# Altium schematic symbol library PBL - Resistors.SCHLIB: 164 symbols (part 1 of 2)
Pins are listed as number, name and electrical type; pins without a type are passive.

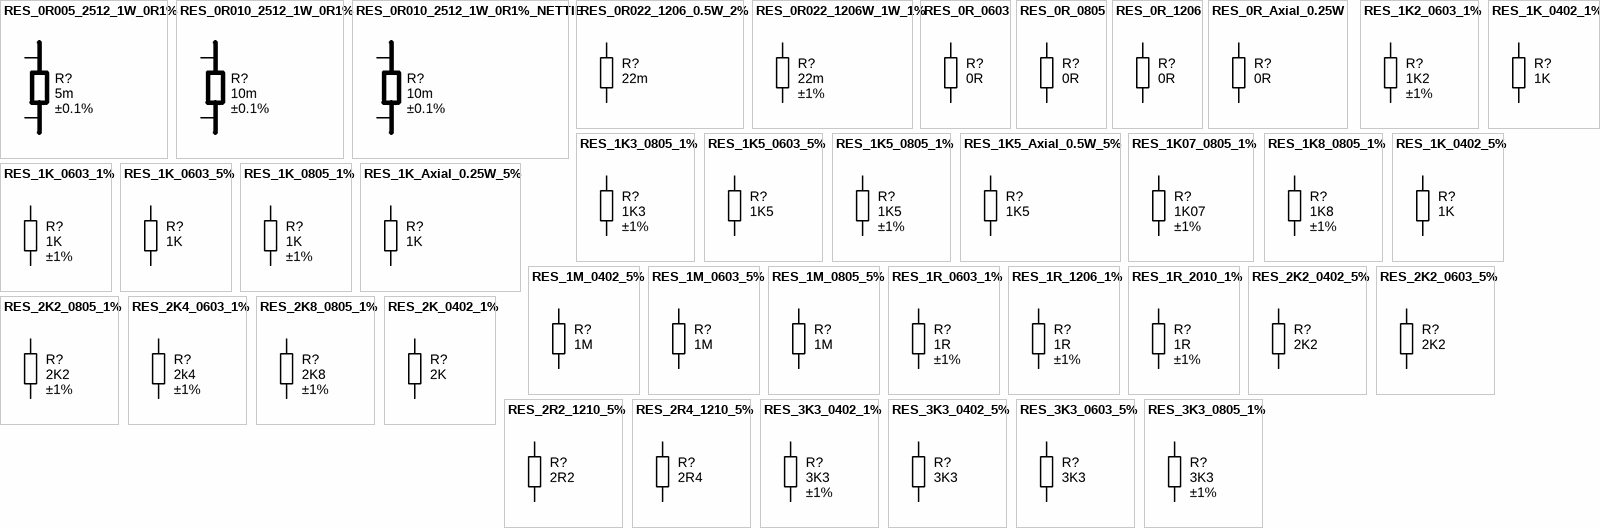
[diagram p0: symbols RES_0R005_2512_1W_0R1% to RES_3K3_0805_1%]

## RES_0R005_2512_1W_0R1%
designator R?, comment value 5m  Tolerance: ±0.1%  (hidden comment: Metal Foil with Kelvin terminations)
RES 0.005 OHM 1W 0.1% 2512 SMD; Manufacturer 1: Vishay Foil Resistors (Division of VPG); Manufacturer Part Number 1: Y14870R00500B9W; Temperature Coefficient: ±15ppm/°C; SCDType: undef
footprint RESC6332X89_SENSE (SMD Sense Resistor with Kelvin terminations, Body 6.3x3.2mm, 2512, IPC Medium Density)
pins: E1 S, E2 S, I1 I, I2 I

## RES_0R010_2512_1W_0R1%
designator R?, comment value 10m  Tolerance: ±0.1%  (hidden comment: Metal Foil with Kelvin terminations)
RES 0.010 OHM 1W 0.1% 2512 SMD; Manufacturer 1: Vishay Foil Resistors (Division of VPG); Manufacturer Part Number 1: Y14870R01000B9W; Temperature Coefficient: ±15ppm/°C; SCDType: undef
footprint RESC6332X89_SENSE (SMD Sense Resistor with Kelvin terminations, Body 6.3x3.2mm, 2512, IPC Medium Density)
pins: E1 S, E2 S, I1 I, I2 I

## RES_0R010_2512_1W_0R1%_NETTIE
designator R?, comment value 10m  Tolerance: ±0.1%  (hidden comment: Metal Foil with Kelvin terminations)  (net tie, no BOM)
RES 0.010 OHM 1W 0.1% 2512 SMD; Manufacturer 1: Vishay Foil Resistors (Division of VPG); Manufacturer Part Number 1: Y14870R01000B9W; Temperature Coefficient: ±15ppm/°C; SCDType: undef
footprint RESC6332X89_SENSE_NETTIE (SMD Sense Resistor with Kelvin terminations, Body 6.3x3.2mm, 2512, IPC Medium Density)
pins: E1 S, E2 S, I1 I, I2 I

## RES_0R022_1206_0.5W_2%
designator R?, comment value 22m  (hidden comment: Thick Film)
Resistor SMD chip 22 milliohm 0.5W 2% 1206; Manufacturer 1: Susumu Co Ltd; Manufacturer Part Number 1: RL1632T-R022-G; Ratings: 1/2W; SCDType: spec
footprint RESC3216X70N (Chip Resistor, Body 3.2x1.6mm, 1206, IPC Medium Density)
pins: 1, 2

## RES_0R022_1206W_1W_1%
designator R?, comment value 22m  Tolerance: ±1%  (hidden comment: Thick film)
RES .022 OHM 1W 1% 1206 SMD; Manufacturer 1: Susumu Co Ltd; Manufacturer Part Number 1: PRL1632-R022-F-T1; Temperature Coefficient: ±100ppm/°C; SCDType: undef
footprint RESC3216X70N (Chip Resistor, Body 3.2x1.6mm, 1206, IPC Medium Density)
pins: 1, 2

## RES_0R_0603
designator R?, comment value 0R  (hidden comment: Thick Film)
Resistor SMD chip 0.0 Ohm 0.1W 0603; Manufacturer 1: Vishay/Dale; Manufacturer Part Number 1: CRCW06030000Z0EA; Tolerance: ±5%; Ratings: 1/10W; SCDType: spec
footprint RESC1608N_ZERO (Chip Resistor, Body 1.6x0.8mm, 0603, IPC Medium Density)
pins: 1, 2

## RES_0R_0805
designator R?, comment value 0R  (hidden comment: Jumper)
Resistor SMD chip 0.0 Ohm 0.125W 0805; Manufacturer 1: Samsung Electro-Mechanics America, Inc; Manufacturer Part Number 1: RC2012J000CS; Ratings: 1/8W; SCDType: spec
footprint RESC2012N_ZERO (Chip Resistor, Body 2.0x1.2mm, 0805, IPC Medium Density)
pins: 1, 2

## RES_0R_1206
designator R?, comment value 0R  (hidden comment: Thick Film)
Resistor SMD chip 0.0 Ohm 0.25W 1206; Manufacturer 1: Vishay/Dale; Manufacturer Part Number 1: CRCW12060000Z0EA; Tolerance: ±5%; Ratings: 1/4W; SCDType: spec*\?
footprint RESC3216N_ZERO (Chip Resistor, Body 3.2x1.6mm, 1206, IPC Medium Density)
pins: 1, 2

## RES_0R_Axial_0.25W
designator R?, comment value 0R  (hidden comment: Carbon Film)
Resistor THD 0.0 Ohm 0.25W Jumper; Manufacturer 1: Yageo; Manufacturer Part Number 1: ZOR-25-R; Ratings: 1/4W; SCDType: spec
footprint RESTH_0.0R_AXIAL-0.6 (Axial Resistor 0 Ohm, Thru-Hole; 2 Leads; 0.6 in Pin Spacing)
pins: 1, 2

## RES_1K2_0603_1%
designator R?, comment value 1K2  Tolerance: ±1%  (hidden comment: Thick Film)
Resistor SMD chip 1.2K Ohm 0.1W 1% 0603; Manufacturer: Yageo; Manufacturer Part Number: RC0603FR-071K2L; Ratings: 1/10W; SCDType: undef
footprint RESC1608X55N (Chip Resistor, Body 1.6x0.8mm, 0603, IPC Medium Density)
pins: 1, 2

## RES_1K3_0805_1%
designator R?, comment value 1K3  Tolerance: ±1%  (hidden comment: Thick Film)
Resistor SMD chip 1.3k Ohm 0.125W 1% 0805; Manufacturer 1: Vishay/Dale; Manufacturer Part Number 1: CRCW08051K30FKEA; Ratings: 1/8W; SCDType: spec
footprint RESC2012X70N (Chip Resistor, Body 2.0x1.2mm, 0805, IPC Medium Density)
pins: 1, 2

## RES_1K5_0603_5%
designator R?, comment value 1K5  (hidden comment: Thick Film)
Resistor SMD chip 1.5k Ohm 0.1W 5% 0603; Manufacturer 1: Yageo; Manufacturer Part Number 1: RC0603JR-071K5L; Ratings: 1/10 W; SCDType: spec
footprint RESC1608X55N (Chip Resistor, Body 1.6x0.8mm, 0603, IPC Medium Density)
pins: 1, 2

## RES_1K5_0805_1%
designator R?, comment value 1K5  Tolerance: ±1%  (hidden comment: Thick Film)
Resistor SMD chip 1.5k Ohm 0.125W 1% 0805; Manufacturer 1: Vishay/Dale; Manufacturer Part Number 1: CRCW08051K50FKEA; Ratings: 1/8W; SCDType: spec
footprint RESC2012X70N (Chip Resistor, Body 2.0x1.2mm, 0805, IPC Medium Density)
pins: 1, 2

## RES_1K5_Axial_0.5W_5%
designator R?, comment value 1K5  (hidden comment: Carbon Film)
Resistor THD Axial 1.5k Ohm 0.5W 5% Carbon Film; Manufacturer 1: Yageo; Manufacturer Part Number 1: CFR-50JB-1K5; Ratings: 1/2W; SCDType: spec
footprint RESTH_AXIAL-0.4
pins: 1, 2

## RES_1K07_0805_1%
designator R?, comment value 1K07  Tolerance: ±1%  (hidden comment: Thick Film)
Resistor SMD chip 1.07K Ohm 0.125W 1% 0805; Manufacturer 1: Panasonic Electronic Components; Manufacturer Part Number 1: ERJ-6ENF1071V; Ratings: 1/8W; SCDType: undef
footprint RESC2012X70N (Chip Resistor, Body 2.0x1.2mm, 0805, IPC Medium Density)
pins: 1, 2

## RES_1K8_0805_1%
designator R?, comment value 1K8  Tolerance: ±1%  (hidden comment: Thick Film)
Resistor SMD chip 1.8k Ohm 0.125W 1% 0805; Manufacturer 1: Vishay/Dale; Manufacturer Part Number 1: CRCW08051K80FKEA; Ratings: 1/8W; SCDType: spec
footprint RESC2012X70N (Chip Resistor, Body 2.0x1.2mm, 0805, IPC Medium Density)
pins: 1, 2

## RES_1K_0402_1%
designator R?, comment value 1K  (hidden comment: Thick Film)
Resistor SMD chip 1k Ohm 0.063W 1% 0402; Manufacturer 1: ROhm; Manufacturer Part Number 1: MCR01MRTF1001; Ratings: 1/16 W; SCDType: spec
footprint RESC1005X40N (Chip Resistor, Body 1.0x0.5mm, EIA 0402, IPC Medium Density)
pins: 1, 2

## RES_1K_0402_5%
designator R?, comment value 1K  (hidden comment: Thick Film)
Resistor SMD chip 1k Ohm 0.063W 5% 0402; Manufacturer 1: Yageo; Manufacturer Part Number 1: RC0402JR-071KL; Ratings: 1/16 W; SCDType: spec
footprint RESC1005X40N (Chip Resistor, Body 1.0x0.5mm, EIA 0402, IPC Medium Density)
pins: 1, 2

## RES_1K_0603_1%
designator R?, comment value 1K  Tolerance: ±1%  (hidden comment: Thick Film)
Resistor SMD chip 1k Ohm 0.1W 1% 0603; Manufacturer 1: Yageo; Manufacturer Part Number 1: RC0603FR-071KL; Ratings: 1/10W; SCDType: spec
footprint RESC1608X55N (Chip Resistor, Body 1.6x0.8mm, 0603, IPC Medium Density)
pins: 1, 2

## RES_1K_0603_5%
designator R?, comment value 1K  (hidden comment: Thick Film)
Resistor SMD chip 1k Ohm 0.1W 5% 0603; Manufacturer 1: Yageo; Manufacturer Part Number 1: RC0603JR-071KL; Ratings: 1/10 W; SCDType: spec
footprint RESC1608X55N (Chip Resistor, Body 1.6x0.8mm, 0603, IPC Medium Density)
pins: 1, 2

## RES_1K_0805_1%
designator R?, comment value 1K  Tolerance: ±1%  (hidden comment: Thick Film)
Resistor SMD chip 1k Ohm 0.125W 1% 0805; Manufacturer 1: Vishay/Dale; Manufacturer Part Number 1: CRCW08051K00FKEA; Ratings: 1/8W; SCDType: spec
footprint RESC2012X70N (Chip Resistor, Body 2.0x1.2mm, 0805, IPC Medium Density)
pins: 1, 2

## RES_1K_Axial_0.25W_5%
designator R?, comment value 1K  (hidden comment: Carbon Film)
Resistor THD Axial 1k Ohm 0.25W 5% Carbon Film; Manufacturer 1: Yageo; Manufacturer Part Number 1: CFR-25JB-1K0; Ratings: 1/4W; SCDType: spec
footprint RESTH_AXIAL-0.4
pins: 1, 2

## RES_1M_0402_5%
designator R?, comment value 1M  (hidden comment: Thick Film)
Resistor SMD chip 1M Ohm 0.063W 5% 0402; Manufacturer 1: Vishay Dale; Manufacturer Part Number 1: CRCW04021M00JNED; Ratings: 1/16 W; Power Rating: 0.063W, 1/16W; SCDType: spec
footprint RESC1005X40N (Chip Resistor, Body 1.0x0.5mm, EIA 0402, IPC Medium Density)
pins: 1, 2

## RES_1M_0603_5%
designator R?, comment value 1M  (hidden comment: Thick Film)
Resistor SMD chip 1M Ohm 0.1W 5% 0603; Manufacturer 1: Vishay Dale; Manufacturer Part Number 1: CRCW06031M00JNEA; Ratings: 1/10 W; SCDType: spec
footprint RESC1608X55N (Chip Resistor, Body 1.6x0.8mm, 0603, IPC Medium Density)
pins: 1, 2

## RES_1M_0805_5%
designator R?, comment value 1M  (hidden comment: Thick Film)
Resistor SMD chip 1M Ohm 0.125W 5% 0805; Manufacturer 1: Vishay/Dale; Manufacturer Part Number 1: CRCW08051M00JNEA; Ratings: 1/8W; SCDType: spec
footprint RESC2012X70N (Chip Resistor, Body 2.0x1.2mm, 0805, IPC Medium Density)
pins: 1, 2

## RES_1R_0603_1%
designator R?, comment value 1R  Tolerance: ±1%  (hidden comment: Thick Film)
Resistor SMD chip 1 Ohm 0.1W 1% 0603; Manufacturer 1: Yageo; Manufacturer Part Number 1: RC0603FR-071RL; Ratings: 1/10W; SCDType: spec
footprint RESC1608X55N (Chip Resistor, Body 1.6x0.8mm, 0603, IPC Medium Density)
pins: 1, 2

## RES_1R_1206_1%
designator R?, comment value 1R  Tolerance: ±1%  (hidden comment: Thick Film)
Resistor SMD chip 1 Ohm 250mW 1% 1206; Manufacturer 1: KOA Speer; Manufacturer Part Number 1: RK73H2BTTD1R00F; Ratings: 1/4W; 200V; Parameter Name: 100 PPM / C; SCDType: spec
footprint RESC3216X70N (Chip Resistor, Body 3.2x1.6mm, 1206, IPC Medium Density)
pins: 1, 2

## RES_1R_2010_1%
designator R?, comment value 1R  Tolerance: ±1%  (hidden comment: Thick Film)
Resistor SMD chip 1 Ohm 1W 1% 2010; Manufacturer 1: Vishay/Dale; Manufacturer Part Number 1: CRCW20101R00FKEFHP; Ratings: 1W; 400V; SCDType: spec
footprint RESC5025X70N (Chip Resistor, Body 5.0x2.5mm, 2010, IPC Medium Density)
pins: 1, 2

## RES_2K2_0402_5%
designator R?, comment value 2K2  (hidden comment: Thick Film)
Resistor SMD chip 2.2k Ohm 0.063W 5% 0402; Manufacturer 1: Vishay Dale; Manufacturer Part Number 1: CRCW04022K20JNED; Ratings: 1/16 W; SCDType: spec
footprint RESC1005X40N (Chip Resistor, Body 1.0x0.5mm, EIA 0402, IPC Medium Density)
pins: 1, 2

## RES_2K2_0603_5%
designator R?, comment value 2K2  (hidden comment: Thick Film)
Resistor SMD chip 2.2k Ohm 0.1W 5% 0603; Manufacturer 1: Yageo; Manufacturer Part Number 1: RC0603JR-072K2L; Ratings: 1/10 W; SCDType: spec; Temperature Coefficient: ±100ppm/°C
footprint RESC1608X55N (Chip Resistor, Body 1.6x0.8mm, 0603, IPC Medium Density)
pins: 1, 2

## RES_2K2_0805_1%
designator R?, comment value 2K2  Tolerance: ±1%  (hidden comment: Thick Film)
Resistor SMD chip 2.2k Ohm 0.125W 1% 0805; Manufacturer 1: Vishay/Dale; Manufacturer Part Number 1: CRCW08052K20FKEA; Ratings: 1/8W; SCDType: spec
footprint RESC2012X70N (Chip Resistor, Body 2.0x1.2mm, 0805, IPC Medium Density)
pins: 1, 2

## RES_2K4_0603_1%
designator R?, comment value 2k4  Tolerance: ±1%  (hidden comment: Thick Film)
Resistor SMD chip 2.4K Ohm 0.1W 1% 0603; Manufacturer: Yageo; Manufacturer Part Number: RC0603FR-072K4L; Ratings: 1/10W; SCDType: undef
footprint RESC1608X55N (Chip Resistor, Body 1.6x0.8mm, 0603, IPC Medium Density)
pins: 1, 2

## RES_2K8_0805_1%
designator R?, comment value 2K8  Tolerance: ±1%  (hidden comment: Thick Film)
Resistor SMD chip 2.8k Ohm 0.125W 1% 0805; Manufacturer 1: Vishay/Dale; Manufacturer Part Number 1: CRCW08052K80FKEA; Ratings: 1/8W; SCDType: spec
footprint RESC2012X70N (Chip Resistor, Body 2.0x1.2mm, 0805, IPC Medium Density)
pins: 1, 2

## RES_2K_0402_1%
designator R?, comment value 2K  (hidden comment: Thick Film)
Resistor SMD chip 2k Ohm 0.063W 1% 0402; Manufacturer 1: ROhm; Manufacturer Part Number 1: MCR01MRTF2001; Ratings: 1/16 W; SCDType: spec
footprint RESC1005X40N (Chip Resistor, Body 1.0x0.5mm, EIA 0402, IPC Medium Density)
pins: 1, 2

## RES_2R2_1210_5%
designator R?, comment value 2R2  (hidden comment: Thick Film)
Resistor SMD chip 2.2 Ohm 0.5W 5% 1210; Manufacturer 1: Panasonic - ECG; Manufacturer Part Number 1: ERJ-14YJ2R2U; Ratings: 1/2 W; SCDType: spec
footprint RESC3225X70N (Chip Resistor, Body 3.2x2.5mm, 1210, IPC Medium Density)
pins: 1, 2

## RES_2R4_1210_5%
designator R?, comment value 2R4  (hidden comment: Thick Film)
Resistor SMD chip 2.4 Ohm 0.5W 5% 1210; Manufacturer 1: Panasonic - ECG; Manufacturer Part Number 1: ERJ-14YJ2R4U; Ratings: 1/2 W; SCDType: spec
footprint RESC3225X70N (Chip Resistor, Body 3.2x2.5mm, 1210, IPC Medium Density)
pins: 1, 2

## RES_3K3_0402_1%
designator R?, comment value 3K3  Tolerance: ±1%  (hidden comment: Thick Film)
Resistor SMD chip 3.3k Ohm 0.063W 1% 0402; Manufacturer 1: Yageo; Manufacturer Part Number 1: RC0402FR-073K3L; Ratings: 1/16 W; 100ppm/°C; SCDType: spec; Temperature Coefficient: ±100ppm/°C
footprint RESC1005X40N (Chip Resistor, Body 1.0x0.5mm, EIA 0402, IPC Medium Density)
pins: 1, 2

## RES_3K3_0402_5%
designator R?, comment value 3K3  (hidden comment: Thick Film)
Resistor SMD chip 3.3k Ohm 0.063W 5% 0402; Manufacturer 1: Yageo; Manufacturer Part Number 1: RC0402JR-073K3L; Ratings: 1/16 W; SCDType: spec
footprint RESC1005X40N (Chip Resistor, Body 1.0x0.5mm, EIA 0402, IPC Medium Density)
pins: 1, 2

## RES_3K3_0603_5%
designator R?, comment value 3K3  (hidden comment: Thick Film)
Resistor SMD chip 3.3k Ohm 0.1W 5% 0603; Manufacturer 1: Yageo; Manufacturer Part Number 1: RC0603JR-073K3L; Ratings: 1/10 W; SCDType: undef
footprint RESC1608X55N (Chip Resistor, Body 1.6x0.8mm, 0603, IPC Medium Density)
pins: 1, 2

## RES_3K3_0805_1%
designator R?, comment value 3K3  Tolerance: ±1%  (hidden comment: Thick Film)
Resistor SMD chip 3.3k Ohm 0.125W 1% 0805; Manufacturer 1: Vishay/Dale; Manufacturer Part Number 1: CRCW08053K30FKEA; Ratings: 1/8W; SCDType: spec
footprint RESC2012X70N (Chip Resistor, Body 2.0x1.2mm, 0805, IPC Medium Density)
pins: 1, 2

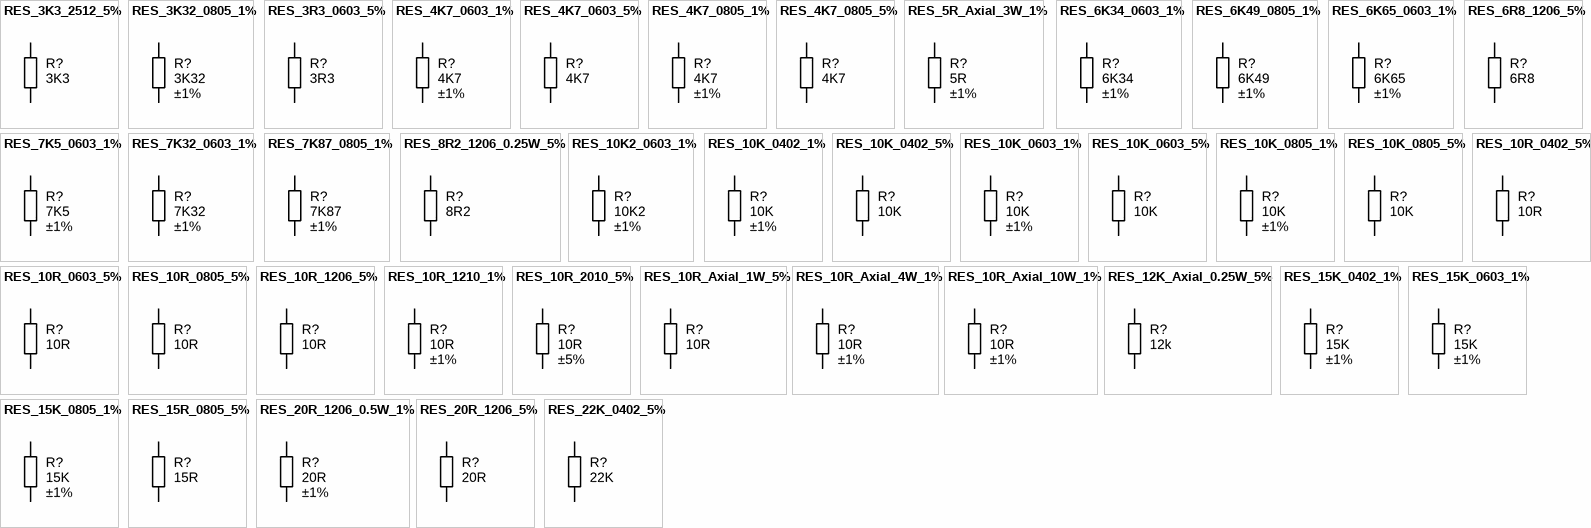
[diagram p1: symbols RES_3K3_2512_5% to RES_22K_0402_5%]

## RES_3K3_2512_5%
designator R?, comment value 3K3  (hidden comment: Thick Film)
Resistor SMD chip 3.3k Ohm 1W 5% 2512; Manufacturer 1: Vishay/Dale; Manufacturer Part Number 1: CRCW25123K30JNEG; SCDType: spec
footprint RESC6332X70N (Chip Resistor, Body 6.3x3.2mm, 2512, IPC Medium Density)
pins: 1, 2

## RES_3K32_0805_1%
designator R?, comment value 3K32  Tolerance: ±1%  (hidden comment: Thick Film)
Resistor SMD chip 3.32K Ohm 0.125W 0805; Manufacturer 1: Panasonic Electronic Components; Manufacturer Part Number 1: ERJ-6ENF3321V; Ratings: 1/8W; SCDType: undef
footprint RESC2012X70N (Chip Resistor, Body 2.0x1.2mm, 0805, IPC Medium Density)
pins: 1, 2

## RES_3R3_0603_5%
designator R?, comment value 3R3  (hidden comment: Thick Film)
Resistor SMD chip 3.3 Ohm 0.1W 5% 0603; Manufacturer 1: Yageo; Manufacturer Part Number 1: RC0603JR-073R3L; Ratings: 1/10 W; SCDType: spec
footprint RESC1608X55N (Chip Resistor, Body 1.6x0.8mm, 0603, IPC Medium Density)
pins: 1, 2

## RES_4K7_0603_1%
designator R?, comment value 4K7  Tolerance: ±1%  (hidden comment: Thick Film)
Resistor SMD chip 4.7K Ohm 0.1W 1% 0603; Manufacturer: Yageo; Manufacturer Part Number: RC0603FR-074K7L; Ratings: 1/10W; SCDType: undef
footprint RESC1608X55N (Chip Resistor, Body 1.6x0.8mm, 0603, IPC Medium Density)
pins: 1, 2

## RES_4K7_0603_5%
designator R?, comment value 4K7  (hidden comment: Thick Film)
Resistor SMD chip 4.7k Ohm 0.1W 5% 0603; Manufacturer 1: Vishay/Dale; Manufacturer Part Number 1: CRCW06034K70JNEA; Ratings: 1/10 W; SCDType: spec
footprint RESC1608X55N (Chip Resistor, Body 1.6x0.8mm, 0603, IPC Medium Density)
pins: 1, 2

## RES_4K7_0805_1%
designator R?, comment value 4K7  Tolerance: ±1%  (hidden comment: Thick Film)
Resistor SMD chip 4.7k Ohm 0.125W 1% 0805; Manufacturer 1: Vishay/Dale; Manufacturer Part Number 1: CRCW08054K70FKEA; Ratings: 1/8W; SCDType: spec
footprint RESC2012X70N (Chip Resistor, Body 2.0x1.2mm, 0805, IPC Medium Density)
pins: 1, 2

## RES_4K7_0805_5%
designator R?, comment value 4K7  (hidden comment: Thick Film)
Resistor SMD chip 4.7k Ohm 0.125W 5% 0805; Manufacturer 1: Yageo; Manufacturer Part Number 1: RC0805JR-074K7L; Ratings: 1/8 W; SCDType: spec
footprint RESC2012X70N (Chip Resistor, Body 2.0x1.2mm, 0805, IPC Medium Density)
pins: 1, 2

## RES_5R_Axial_3W_1%
designator R?, comment value 5R  Tolerance: ±1%  (hidden comment: Wirewound)
Resistor THD 5 Ohm 3W 1% Wirewound; Manufacturer 1: Vishay/Dale; Manufacturer Part Number 1: RS02B5R000FE70; SCDType: spec
footprint RESTH_AXIAL_RS02B (Axial Resistor Thru-Hole; 2 Leads)
pins: 1, 2

## RES_6K34_0603_1%
designator R?, comment value 6K34  Tolerance: ±1%  (hidden comment: Thick Film)
Resistor SMD chip 6.34k Ohm 0.1W 1% 0603; Manufacturer 1: Yageo; Manufacturer Part Number 1: RC0603FR-076K34L; Ratings: 1/10W; SCDType: spec
footprint RESC1608X55N (Chip Resistor, Body 1.6x0.8mm, 0603, IPC Medium Density)
pins: 1, 2

## RES_6K49_0805_1%
designator R?, comment value 6K49  Tolerance: ±1%  (hidden comment: Thick Film)
Resistor SMD chip 6.49k Ohm 0.125W 1% 0805; Manufacturer: Vishay/Dale; Manufacturer Part Number: CRCW08056K49FKEA; Ratings: 1/8W; SCDType: spec
footprint RESC2012X70N (Chip Resistor, Body 2.0x1.2mm, 0805, IPC Medium Density)
pins: 1, 2

## RES_6K65_0603_1%
designator R?, comment value 6K65  Tolerance: ±1%  (hidden comment: Thick Film)
Resistor SMD chip 6.65k Ohm 0.1W 1% 0603; Manufacturer 1: Yageo; Manufacturer Part Number 1: RC0603FR-076K65L; Ratings: 1/10W; SCDType: spec
footprint RESC1608X55N (Chip Resistor, Body 1.6x0.8mm, 0603, IPC Medium Density)
pins: 1, 2

## RES_6R8_1206_5%
designator R?, comment value 6R8  (hidden comment: Thick Film)
Resistor SMD chip 6.8 Ohm 0.25W 5% 1206; Manufacturer 1: Vishay/Dale; Manufacturer Part Number 1: CRCW12066R80JNEA; Ratings: 1/4W; SCDType: spec
footprint RESC3216X70N (Chip Resistor, Body 3.2x1.6mm, 1206, IPC Medium Density)
pins: 1, 2

## RES_7K5_0603_1%
designator R?, comment value 7K5  Tolerance: ±1%  (hidden comment: Thick Film)
Resistor SMD chip 7.5K Ohm 0.1W 1% 0603; Manufacturer: Yageo; Manufacturer Part Number: RC0603FR-077K5L; Ratings: 1/10W; SCDType: undef
footprint RESC1608X55N (Chip Resistor, Body 1.6x0.8mm, 0603, IPC Medium Density)
pins: 1, 2

## RES_7K32_0603_1%
designator R?, comment value 7K32  Tolerance: ±1%  (hidden comment: Thick Film)
Resistor SMD chip 7.32 kOhm 0.1W 1% 0603; Manufacturer 1: Panasonic Electronic Components; Manufacturer Part Number 1: ERJ-3EKF7321V; Ratings: 1/10W; SCDType: Spec
footprint RESC1608X55N (Chip Resistor, Body 1.6x0.8mm, 0603, IPC Medium Density)
pins: 1, 2

## RES_7K87_0805_1%
designator R?, comment value 7K87  Tolerance: ±1%  (hidden comment: Thick Film)
Resistor SMD chip 7.87k Ohm 0.125W 1% 0805; Manufacturer 1: Vishay/Dale; Manufacturer Part Number 1: CRCW08057K87FKEA; Ratings: 1/8W; SCDType: spec
footprint RESC2012X70N (Chip Resistor, Body 2.0x1.2mm, 0805, IPC Medium Density)
pins: 1, 2

## RES_8R2_1206_0.25W_5%
designator R?, comment value 8R2  (hidden comment: Thick Film)
Resistor SMD chip 8.2 Ohm 0.25W 5% 1206; Manufacturer 1: Royal Ohm; Manufacturer Part Number 1: 1206WAJ08R2; Ratings: 1/4 W; SCDType: spec
footprint RESC3216X70N (Chip Resistor, Body 3.2x1.6mm, 1206, IPC Medium Density)
pins: 1, 2

## RES_10K2_0603_1%
designator R?, comment value 10K2  Tolerance: ±1%  (hidden comment: Thick Film)
Resistor SMD chip 10.2K Ohm 0.1W 1% 0603; Manufacturer 1: Yageo; Manufacturer Part Number 1: RC0603FR-0710K2L; Ratings: 1/10W; Parameter Name: ±100ppm/°C; SCDType: undef
footprint RESC1608X55N (Chip Resistor, Body 1.6x0.8mm, 0603, IPC Medium Density)
pins: 1, 2

## RES_10K_0402_1%
designator R?, comment value 10K  Tolerance: ±1%  (hidden comment: Thick Film)
Resistor SMD chip 10k Ohm 0.063W 1% 0402; Manufacturer 1: Vishay Dale; Manufacturer Part Number 1: CRCW040210K0FKED; Ratings: 1/16 W; SCDType: spec
footprint RESC1005X40N (Chip Resistor, Body 1.0x0.5mm, EIA 0402, IPC Medium Density)
pins: 1, 2

## RES_10K_0402_5%
designator R?, comment value 10K  (hidden comment: Thick Film)
Resistor SMD chip 10k Ohm 0.063W 5% 0402; Manufacturer 1: Vishay Dale; Manufacturer Part Number 1: CRCW040210K0FKED; Ratings: 1/16 W; SCDType: undef
footprint RESC1005X40N (Chip Resistor, Body 1.0x0.5mm, EIA 0402, IPC Medium Density)
pins: 1, 2

## RES_10K_0603_1%
designator R?, comment value 10K  Tolerance: ±1%  (hidden comment: Thick Film)
Resistor SMD chip 10k Ohm 0.1W 1% 0603; Manufacturer 1: Yageo; Manufacturer Part Number 1: RC0603FR-0710KL; Ratings: 1/10W; SCDType: spec
footprint RESC1608X55N (Chip Resistor, Body 1.6x0.8mm, 0603, IPC Medium Density)
pins: 1, 2

## RES_10K_0603_5%
designator R?, comment value 10K  (hidden comment: Thick Film)
Resistor SMD chip 10k Ohm 0.1W 5% 0603; Manufacturer 1: Yageo; Manufacturer Part Number 1: RC0603JR-0710KL; Ratings: 1/10 W; SCDType: spec
footprint RESC1608X55N (Chip Resistor, Body 1.6x0.8mm, 0603, IPC Medium Density)
pins: 1, 2

## RES_10K_0805_1%
designator R?, comment value 10K  Tolerance: ±1%  (hidden comment: Thick Film)
Resistor SMD chip 10k Ohm 0.125W 1% 0805; Manufacturer 1: Vishay/Dale; Manufacturer Part Number 1: CRCW080510K0FKEA; Ratings: 1/8W; SCDType: spec
footprint RESC2012X70N (Chip Resistor, Body 2.0x1.2mm, 0805, IPC Medium Density)
pins: 1, 2

## RES_10K_0805_5%
designator R?, comment value 10K  (hidden comment: Thick Film)
Resistor SMD chip 10k Ohm 0.125W 5% 0805; Manufacturer 1: Yageo; Manufacturer Part Number 1: RC0805JR-0710KL; Ratings: 1/8 W; SCDType: spec
footprint RESC2012X70N (Chip Resistor, Body 2.0x1.2mm, 0805, IPC Medium Density)
pins: 1, 2

## RES_10R_0402_5%
designator R?, comment value 10R  (hidden comment: Thick Film)
Resistor SMD chip 10 Ohm 0.063W 5% 0402; Manufacturer 1: Yageo; Manufacturer Part Number 1: RC0402JR-0710RL; Ratings: 1/16 W; SCDType: spec
footprint RESC1005X40N (Chip Resistor, Body 1.0x0.5mm, EIA 0402, IPC Medium Density)
pins: 1, 2

## RES_10R_0603_5%
designator R?, comment value 10R  (hidden comment: Thick Film)
Resistor SMD chip 10 Ohm 0.1W 5% 0603; Manufacturer 1: Yageo; Manufacturer Part Number 1: RC0603JR-0710RL; Ratings: 1/10 W; SCDType: spec
footprint RESC1608X55N (Chip Resistor, Body 1.6x0.8mm, 0603, IPC Medium Density)
pins: 1, 2

## RES_10R_0805_5%
designator R?, comment value 10R  (hidden comment: Thick Film)
Resistor SMD chip 10 Ohm 0.125W 5% 0805; Manufacturer 1: Vishay/Dale; Manufacturer Part Number 1: CRCW080510R0JNEA; Ratings: 1/8W; SCDType: spec
footprint RESC2012X70N (Chip Resistor, Body 2.0x1.2mm, 0805, IPC Medium Density)
pins: 1, 2

## RES_10R_1206_5%
designator R?, comment value 10R  (hidden comment: Thick Film)
Resistor SMD chip 10 Ohm 0.25W 5% 1206; Manufacturer 1: Samsung Electro-Mechanics America, Inc; Manufacturer Part Number 1: RC3216J100CS; Ratings: 1/4W; SCDType: spec
footprint RESC3216X70N (Chip Resistor, Body 3.2x1.6mm, 1206, IPC Medium Density)
pins: 1, 2

## RES_10R_1210_1%
designator R?, comment value 10R  Tolerance: ±1%  (hidden comment: Thick Film)
Resistor SMD chip 10 Ohm 0.5W 1% 1210; Manufacturer 1: Panasonic - ECG; Manufacturer Part Number 1: ERJ-14NF10R0U; Ratings: 1/2W; SCDType: spec
footprint RESC3225X70N (Chip Resistor, Body 3.2x2.5mm, 1210, IPC Medium Density)
pins: 1, 2

## RES_10R_2010_5%
designator R?, comment value 10R  Tolerance: ±5%  (hidden comment: Thick Film)
Resistor SMD chip 10 Ohm 0.25W 5% 2010; Manufacturer 1: Vishay/Dale; Manufacturer Part Number 1: CRCW120610R0JNEA; Ratings: 1/4W; SCDType: undef
footprint RESC5025X70N (Chip Resistor, Body 5.0x2.5mm, 2010, IPC Medium Density)
pins: 1, 2

## RES_10R_Axial_1W_5%
designator R?, comment value 10R  (hidden comment: Metal Film)
Resistor THD 10 Ohm 1W 5% Metal Film; Manufacturer 1: Vishay/BC Components; Manufacturer Part Number 1: PR01000101009JR500; SCDType: spec
footprint AXIAL-0.6 (Axial Device, Thru-Hole; 2 Leads; 0.6 in Pin Spacing)
pins: 1, 2

## RES_10R_Axial_4W_1%
designator R?, comment value 10R  Tolerance: ±1%  (hidden comment: Wirewound)
Resistor THD 10 Ohm 4W 1% Wirewound; Manufacturer Part Number 1: MRA-0510R00FE12; Manufacturer 1: Vishay Dale; Ratings: 4W; 30ppm; Parameter Name: 0.167" Dia x 0.562" L (4.24mm x 14.27mm); SCDType: undef
footprint RESTH_AXIAL_MRA-05 (MRA-05 Axial Resistor Thru-Hole; 2 Leads)
pins: 1, 2

## RES_10R_Axial_10W_1%
designator R?, comment value 10R  Tolerance: ±1%  (hidden comment: Wirewound)
Resistor THD 10 Ohm 10W 1% Wirewound; Manufacturer 1: Vishay/Dale; Manufacturer Part Number 1: RS01010R00FE73; SCDType: spec
footprint RESTH_AXIAL_RS010 (Axial Resistor Thru-Hole; 2 Leads)
pins: 1, 2

## RES_12K_Axial_0.25W_5%
designator R?, comment value 12k  (hidden comment: Carbon Film)
Resistor THD Axial 12k Ohm 0.25W 5% Carbon Film; Manufacturer 1: Yageo; Manufacturer Part Number 1: CFR-25JB-12K; Ratings: 1/4W; SCDType: spec
footprint RESTH_AXIAL-0.4
pins: 1, 2

## RES_15K_0402_1%
designator R?, comment value 15K  Tolerance: ±1%  (hidden comment: Thick Film)
Resistor SMD chip 15k Ohm 0.063W 1% 0402; Manufacturer 1: Vishay Dale; Manufacturer Part Number 1: CRCW040215K0FKED; Ratings: 1/16 W; SCDType: spec
footprint RESC1005X40N (Chip Resistor, Body 1.0x0.5mm, EIA 0402, IPC Medium Density)
pins: 1, 2

## RES_15K_0603_1%
designator R?, comment value 15K  Tolerance: ±1%  (hidden comment: Thick Film)
Resistor SMD chip 15k Ohm 0.1W 1% 0603; Manufacturer 1: Rohm Semiconductor; Manufacturer Part Number 1: MCR03ERTF1502; Ratings: 1/10 W; SCDType: spec
footprint RESC1608X55N (Chip Resistor, Body 1.6x0.8mm, 0603, IPC Medium Density)
pins: 1, 2

## RES_15K_0805_1%
designator R?, comment value 15K  Tolerance: ±1%  (hidden comment: Thick Film)
Resistor SMD chip 15k Ohm 0.125W 1% 0805; Manufacturer 1: Vishay/Dale; Manufacturer Part Number 1: CRCW080515K0FKEA; Ratings: 1/8W; SCDType: spec
footprint RESC2012X70N (Chip Resistor, Body 2.0x1.2mm, 0805, IPC Medium Density)
pins: 1, 2

## RES_15R_0805_5%
designator R?, comment value 15R  (hidden comment: Thick Film)
Resistor SMD chip 15 Ohm 0.125W 5% 0805; Manufacturer 1: Yageo; Manufacturer Part Number 1: RC0805JR-0715RL; Ratings: 1/8W; SCDType: spec
footprint RESC2012X70N (Chip Resistor, Body 2.0x1.2mm, 0805, IPC Medium Density)
pins: 1, 2

## RES_20R_1206_0.5W_1%
designator R?, comment value 20R  Tolerance: ±1%  (hidden comment: Thick Film)
Resistor SMD chip 20 Ohm 0.5W 1% 1206; Manufacturer 1: Stackpole Electronics Inc; Manufacturer Part Number 1: RNCP1206FTD20R0; Ratings: 1/2W; SCDType: undef
footprint RESC3216X70N (Chip Resistor, Body 3.2x1.6mm, 1206, IPC Medium Density)
pins: 1, 2

## RES_20R_1206_5%
designator R?, comment value 20R  (hidden comment: Thick Film)
Resistor SMD chip 20 Ohm 0.25W 5% 1206; Manufacturer 1: Yageo; Manufacturer Part Number 1: RC1206JR-0720RL; Ratings: 1/4W; SCDType: spec
footprint RESC3216X70N (Chip Resistor, Body 3.2x1.6mm, 1206, IPC Medium Density)
pins: 1, 2

## RES_22K_0402_5%
designator R?, comment value 22K  (hidden comment: Thick Film)
Resistor SMD chip 22k Ohm 0.063W 5% 0402; Manufacturer 1: Yageo; Manufacturer Part Number 1: RC0402JR-0722KL; Ratings: 1/16 W; SCDType: spec
footprint RESC1005X40N (Chip Resistor, Body 1.0x0.5mm, EIA 0402, IPC Medium Density)
pins: 1, 2

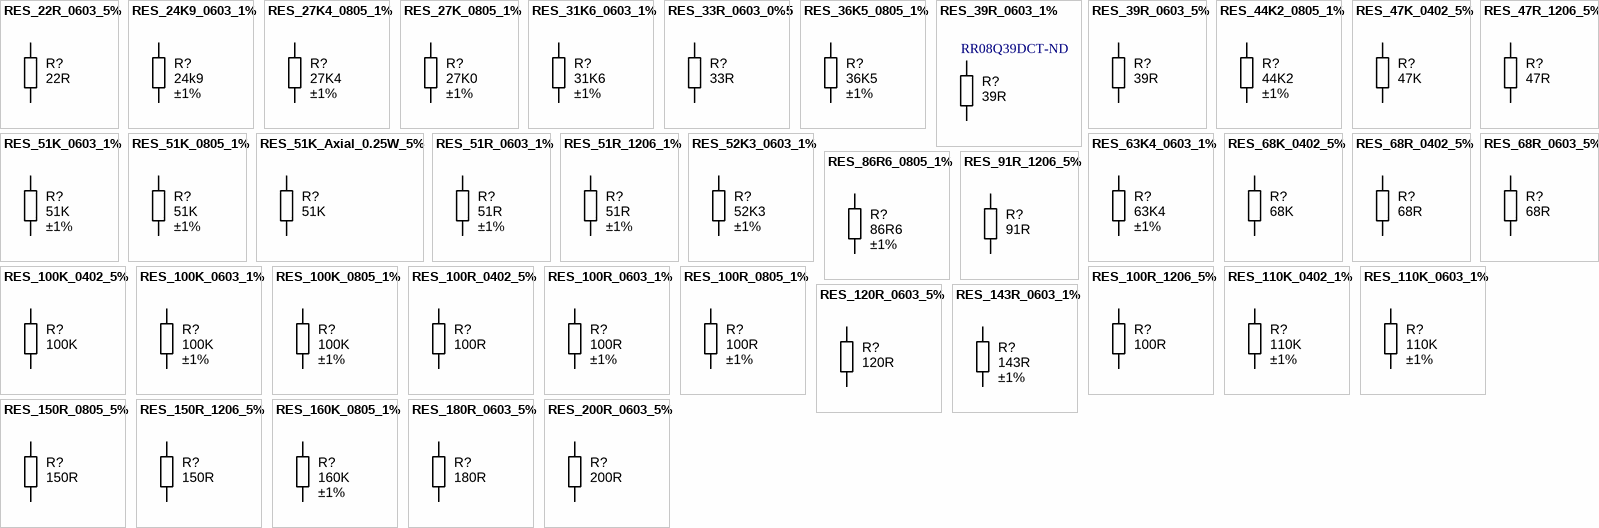
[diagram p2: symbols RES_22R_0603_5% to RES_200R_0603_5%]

## RES_22R_0603_5%
designator R?, comment value 22R  (hidden comment: Thick Film)
Resistor SMD chip 22 Ohm 0.1W 5% 0603; Manufacturer 1: Yageo; Manufacturer Part Number 1: RC0603JR-0722RL; Ratings: 1/10W; SCDType: spec; Temperature Coefficient: ±100ppm/°C
footprint RESC1608X55N (Chip Resistor, Body 1.6x0.8mm, 0603, IPC Medium Density)
pins: 1, 2

## RES_24K9_0603_1%
designator R?, comment value 24k9  Tolerance: ±1%  (hidden comment: Thick Film)
Resistor SMD chip 24.9k Ohm 0.1W 1% 0603; Ratings: 1/10 W; SCDType: spec
footprint RESC1608X55N (Chip Resistor, Body 1.6x0.8mm, 0603, IPC Medium Density)
pins: 1, 2

## RES_27K4_0805_1%
designator R?, comment value 27K4  Tolerance: ±1%  (hidden comment: Thick Film)
Resistor SMD chip 27.4k Ohm 0.125W 1% 0805; Manufacturer 1: Vishay/Dale; Manufacturer Part Number 1: CRCW080527K4FKEA; Ratings: 1/8W; SCDType: spec
footprint RESC2012X70N (Chip Resistor, Body 2.0x1.2mm, 0805, IPC Medium Density)
pins: 1, 2

## RES_27K_0805_1%
designator R?, comment value 27K0  Tolerance: ±1%  (hidden comment: Thick Film)
Resistor SMD chip 27.0k Ohm 0.125W 1% 0805; Manufacturer 1: Vishay/Dale; Manufacturer Part Number 1: CRCW080527K0FKEA; Ratings: 1/8W; SCDType: spec
footprint RESC2012X70N (Chip Resistor, Body 2.0x1.2mm, 0805, IPC Medium Density)
pins: 1, 2

## RES_31K6_0603_1%
designator R?, comment value 31K6  Tolerance: ±1%  (hidden comment: Thick Film)
Resistor SMD chip 31.6k Ohm 0.1W 1% 0603; Manufacturer 1: Yageo; Manufacturer Part Number 1: RC0603FR-0731K6L; Ratings: 1/10W; SCDType: spec
footprint RESC1608X55N (Chip Resistor, Body 1.6x0.8mm, 0603, IPC Medium Density)
pins: 1, 2

## RES_33R_0603_0%5
designator R?, comment value 33R  (hidden comment: Thick Film)
Resistor SMD chip 33 Ohm 0.1W 0.5% 0603; Manufacturer 1: Susumu; Manufacturer Part Number 1: RR0816Q-330-D; Ratings: 1/10 W; SCDType: spec
footprint RESC1608X55N (Chip Resistor, Body 1.6x0.8mm, 0603, IPC Medium Density)
pins: 1, 2

## RES_36K5_0805_1%
designator R?, comment value 36K5  Tolerance: ±1%  (hidden comment: Thick Film)
Resistor SMD chip 36.5k Ohm 0.125W 1% 0805; Manufacturer 1: Vishay/Dale; Manufacturer Part Number 1: CRCW080536K5FKEA; Ratings: 1/8W; SCDType: spec
footprint RESC2012X70N (Chip Resistor, Body 2.0x1.2mm, 0805, IPC Medium Density)
pins: 1, 2

## RES_39R_0603_1%
designator R?, comment value 39R  Supplier Part Number 2: RR08Q39DCT-ND  (hidden comment: Thick Film)
Resistor SMD chip 39 Ohm 0.1W 1% 0603; Manufacturer 1: Yageo; Ratings: 1/10 W; SCDType: spec
footprint RESC1608X55N (Chip Resistor, Body 1.6x0.8mm, 0603, IPC Medium Density)
pins: 1, 2

## RES_39R_0603_5%
designator R?, comment value 39R  (hidden comment: Thick Film)
Resistor SMD chip 39 Ohm 0.1W 5% 0603; Manufacturer 1: Vishay Dale; Manufacturer Part Number 1: CRCW060339R0JNEA; Ratings: 1/10 W; SCDType: spec
footprint RESC1608X55N (Chip Resistor, Body 1.6x0.8mm, 0603, IPC Medium Density)
pins: 1, 2

## RES_44K2_0805_1%
designator R?, comment value 44K2  Tolerance: ±1%  (hidden comment: Thick Film)
Resistor SMD chip 44.2k Ohm 0.125W 1% 0805; Manufacturer 1: Vishay/Dale; Manufacturer Part Number 1: CRCW080544K2FKEA; Ratings: 1/8W; SCDType: spec
footprint RESC2012X70N (Chip Resistor, Body 2.0x1.2mm, 0805, IPC Medium Density)
pins: 1, 2

## RES_47K_0402_5%
designator R?, comment value 47K  (hidden comment: Thick Film)
Resistor SMD chip 47K Ohm 0.063W 5% 0402; Manufacturer 1: Yageo; Manufacturer Part Number 1: RC0402FR-0747KL; Ratings: 1/16 W; SCDType: spec
footprint RESC1005X40N (Chip Resistor, Body 1.0x0.5mm, EIA 0402, IPC Medium Density)
pins: 1, 2

## RES_47R_1206_5%
designator R?, comment value 47R  (hidden comment: Thick Film)
Resistor SMD chip 47 Ohm 0.25W 5% 1206; Manufacturer 1: Yageo; Manufacturer Part Number 1: RC1206JR-0747RL; Ratings: 1/4W; Voltage Rating: 200 Volts; SCDType: spec
footprint RESC3216X70N (Chip Resistor, Body 3.2x1.6mm, 1206, IPC Medium Density)
pins: 1, 2

## RES_51K_0603_1%
designator R?, comment value 51K  Tolerance: ±1%  (hidden comment: Thick Film)
Resistor SMD chip 51k Ohm 0.1W 1% 0603; Manufacturer 1: Yageo; Manufacturer Part Number 1: RC0603FR-0751KL; Ratings: 1/10W; SCDType: spec
footprint RESC1608X55N (Chip Resistor, Body 1.6x0.8mm, 0603, IPC Medium Density)
pins: 1, 2

## RES_51K_0805_1%
designator R?, comment value 51K  Tolerance: ±1%  (hidden comment: Thick Film)
Resistor SMD chip 51k Ohm 0.125W 1% 0805; Manufacturer 1: Yageo; Manufacturer Part Number 1: RC0805FR-0751KL; Ratings: 1/8W; SCDType: spec
footprint RESC2012X70N (Chip Resistor, Body 2.0x1.2mm, 0805, IPC Medium Density)
pins: 1, 2

## RES_51K_Axial_0.25W_5%
designator R?, comment value 51K  (hidden comment: Carbon Film)
Resistor THD Axial 51k Ohm 0.25W 5% Carbon Film; Manufacturer 1: Yageo; Manufacturer Part Number 1: CFR-25JB-51K; Ratings: 1/4W; SCDType: spec
footprint RESTH_AXIAL-0.4
pins: 1, 2

## RES_51R_0603_1%
designator R?, comment value 51R  Tolerance: ±1%  (hidden comment: Thick Film)
Resistor SMD chip 51 Ohm 0.1W 1% 0603; Manufacturer 1: Yageo; Manufacturer Part Number 1: RC0603FR-0751RL; Ratings: 1/10 W; SCDType: spec
footprint RESC1608X55N (Chip Resistor, Body 1.6x0.8mm, 0603, IPC Medium Density)
pins: 1, 2

## RES_51R_1206_1%
designator R?, comment value 51R  Tolerance: ±1%  (hidden comment: Thick Film)
Resistor SMD chip 51 Ohm 0.25W 1% 1206; Manufacturer 1: Vishay/Dale; Manufacturer Part Number 1: CRCW120651R0JNEA; Ratings: 1/4W; SCDType: spec
footprint RESC3216X70N (Chip Resistor, Body 3.2x1.6mm, 1206, IPC Medium Density)
pins: 1, 2

## RES_52K3_0603_1%
designator R?, comment value 52K3  Tolerance: ±1%  (hidden comment: Thick Film)
Resistor SMD chip 52.3K Ohm 0.1W 1% 0603; Manufacturer 1: Yageo; Manufacturer Part Number 1: RC0603FR-0752K3L; Ratings: 1/10W; Parameter Name: ±100ppm/°C; SCDType: undef
footprint RESC1608X55N (Chip Resistor, Body 1.6x0.8mm, 0603, IPC Medium Density)
pins: 1, 2

## RES_63K4_0603_1%
designator R?, comment value 63K4  Tolerance: ±1%  (hidden comment: Thick Film)
Resistor SMD chip 63.4K Ohm 0.1W 1% 0603; Manufacturer 1: Yageo; Manufacturer Part Number 1: RC0603FR-0763K4L; Ratings: 1/10W; SCDType: spec
footprint RESC1608X55N (Chip Resistor, Body 1.6x0.8mm, 0603, IPC Medium Density)
pins: 1, 2

## RES_68K_0402_5%
designator R?, comment value 68K  (hidden comment: Thick Film)
Resistor SMD chip 68K Ohm 0.063W 5% 0402; Manufacturer 1: Yageo; Manufacturer Part Number 1: RC0402FR-0768KL; Ratings: 1/16 W; SCDType: spec
footprint RESC1005X40N (Chip Resistor, Body 1.0x0.5mm, EIA 0402, IPC Medium Density)
pins: 1, 2

## RES_68R_0402_5%
designator R?, comment value 68R  (hidden comment: Thick Film)
Resistor SMD chip 68 Ohm 0.063W 5% 0402; Manufacturer 1: Yageo; Manufacturer Part Number 1: RC0402JR-0768RL; Ratings: 1/16 W; SCDType: spec
footprint RESC1005X40N (Chip Resistor, Body 1.0x0.5mm, EIA 0402, IPC Medium Density)
pins: 1, 2

## RES_68R_0603_5%
designator R?, comment value 68R  (hidden comment: Thick Film)
Resistor SMD chip 68 Ohm 0.1W 5% 0603; Manufacturer 1: Yageo; Manufacturer Part Number 1: RC0603JR-0768RL; Ratings: 1/10 W; SCDType: spec
footprint RESC1608X55N (Chip Resistor, Body 1.6x0.8mm, 0603, IPC Medium Density)
pins: 1, 2

## RES_86R6_0805_1%
designator R?, comment value 86R6  Tolerance: ±1%  (hidden comment: Thick Film)
Resistor SMD chip 86.6 Ohm 0.125W 1% 0805; Manufacturer: Vishay/Dale; Manufacturer Part Number: CRCW080586R6FKEA; Ratings: 1/8W; SCDType: spec
footprint RESC2012X70N (Chip Resistor, Body 2.0x1.2mm, 0805, IPC Medium Density)
pins: 1, 2

## RES_91R_1206_5%
designator R?, comment value 91R  (hidden comment: Thin Film)
Resistor SMD chip 91 Ohm 0.25W 5% 1206; Manufacturer 1: Yageo; Manufacturer Part Number 1: RC1206JR-0791RL; Ratings: 1/4 W; SCDType: spec
footprint RESC3216X70N (Chip Resistor, Body 3.2x1.6mm, 1206, IPC Medium Density)
pins: 1, 2

## RES_100K_0402_5%
designator R?, comment value 100K  (hidden comment: Thick Film)
Resistor SMD chip 100k Ohm 0.063W 5% 0402; Manufacturer 1: Vishay Dale; Manufacturer Part Number 1: CRCW0402100KJNED; Ratings: 1/16 W; SCDType: undef
footprint RESC1005X40N (Chip Resistor, Body 1.0x0.5mm, EIA 0402, IPC Medium Density)
pins: 1, 2

## RES_100K_0603_1%
designator R?, comment value 100K  Tolerance: ±1%  (hidden comment: Thick Film)
Resistor SMD chip 100k Ohm 0.1W 1% 0603; Manufacturer 1: Vishay/Dale; Manufacturer Part Number 1: CRCW0603100KFKEA; Ratings: 1/10W; SCDType: spec
footprint RESC1608X55N (Chip Resistor, Body 1.6x0.8mm, 0603, IPC Medium Density)
pins: 1, 2

## RES_100K_0805_1%
designator R?, comment value 100K  Tolerance: ±1%  (hidden comment: Thick Film)
Resistor SMD chip 100k Ohm 0.125W 1% 0805; Manufacturer 1: Vishay/Dale; Manufacturer Part Number 1: CRCW0805100KFKEA; Ratings: 1/8W; SCDType: spec
footprint RESC2012X70N (Chip Resistor, Body 2.0x1.2mm, 0805, IPC Medium Density)
pins: 1, 2

## RES_100R_0402_5%
designator R?, comment value 100R  (hidden comment: Thick Film)
Resistor SMD chip 100 Ohm 0.063W 5% 0402; Manufacturer 1: Yageo; Manufacturer Part Number 1: RC0402JR-07100RL; Ratings: 1/16 W; SCDType: spec
footprint RESC1005X40N (Chip Resistor, Body 1.0x0.5mm, EIA 0402, IPC Medium Density)
pins: 1, 2

## RES_100R_0603_1%
designator R?, comment value 100R  Tolerance: ±1%  (hidden comment: Thick Film)
Resistor SMD chip 100 Ohm 0.1W 1% 0603; Manufacturer 1: Yageo; Manufacturer Part Number 1: RC0603FR-07100RL; Ratings: 1/10 W; SCDType: spec
footprint RESC1608X55N (Chip Resistor, Body 1.6x0.8mm, 0603, IPC Medium Density)
pins: 1, 2

## RES_100R_0805_1%
designator R?, comment value 100R  Tolerance: ±1%  (hidden comment: Thick Film)
Resistor SMD chip 100 Ohm 0.125W 1% 0805; Manufacturer 1: Yageo; Manufacturer Part Number 1: RC0805FR-07100RL; Ratings: 1/8 W; SCDType: spec
footprint RESC2012X70N (Chip Resistor, Body 2.0x1.2mm, 0805, IPC Medium Density)
pins: 1, 2

## RES_100R_1206_5%
designator R?, comment value 100R  (hidden comment: Thick Film)
Resistor SMD chip 100 Ohm 0.25W 5% 1206; Manufacturer 1: Vishay/Dale; Manufacturer Part Number 1: CRCW1206100RJNEA; SCDType: spec
footprint RESC3216X70N (Chip Resistor, Body 3.2x1.6mm, 1206, IPC Medium Density)
pins: 1, 2

## RES_110K_0402_1%
designator R?, comment value 110K  Tolerance: ±1%  (hidden comment: Thick Film)
Resistor SMD chip 110k Ohm 0.063W 1% 0402; Manufacturer 1: Vishay Dale; Manufacturer Part Number 1: CRCW0402110KFKED; Ratings: 1/16 W; SCDType: spec
footprint RESC1005X40N (Chip Resistor, Body 1.0x0.5mm, EIA 0402, IPC Medium Density)
pins: 1, 2

## RES_110K_0603_1%
designator R?, comment value 110K  Tolerance: ±1%  (hidden comment: Thick Film)
Resistor SMD chip 110K Ohm 0.1W 1% 0603; Manufacturer 1: Yageo; Manufacturer Part Number 1: RC0603FR-07110KL; Ratings: 1/10W; SCDType: undef
footprint RESC1608X55N (Chip Resistor, Body 1.6x0.8mm, 0603, IPC Medium Density)
pins: 1, 2

## RES_120R_0603_5%
designator R?, comment value 120R  (hidden comment: Thick Film)
Resistor SMD chip 120 Ohm 0.1W 5% 0603; Manufacturer 1: Vishay Dale; Manufacturer Part Number 1: CRCW0603120RJNEA; Ratings: 1/10 W; SCDType: spec
footprint RESC1608X55N (Chip Resistor, Body 1.6x0.8mm, 0603, IPC Medium Density)
pins: 1, 2

## RES_143R_0603_1%
designator R?, comment value 143R  Tolerance: ±1%  (hidden comment: Thin Film)
Resistor SMD chip 143 Ohm 0.1W 1% 0603; Manufacturer 1: Yageo; Manufacturer Part Number 1: RC0603FR-07143RL; Ratings: 1/10 W; SCDType: spec
footprint RESC1608X55N (Chip Resistor, Body 1.6x0.8mm, 0603, IPC Medium Density)
pins: 1, 2

## RES_150R_0805_5%
designator R?, comment value 150R  (hidden comment: Thick Film)
Resistor SMD chip 150 Ohm 0.125W 5% 0805; Manufacturer 1: Vishay/Dale; Manufacturer Part Number 1: CRCW0805150RJNEA; Ratings: 1/8W; SCDType: spec
footprint RESC2012X70N (Chip Resistor, Body 2.0x1.2mm, 0805, IPC Medium Density)
pins: 1, 2

## RES_150R_1206_5%
designator R?, comment value 150R  (hidden comment: Thin Film)
Resistor SMD chip 150 Ohm 0.25W 5% 1206; Manufacturer 1: Yageo; Manufacturer Part Number 1: RC1206JR-07150RL; Ratings: 1/4 W; SCDType: spec
footprint RESC3216X70N (Chip Resistor, Body 3.2x1.6mm, 1206, IPC Medium Density)
pins: 1, 2

## RES_160K_0805_1%
designator R?, comment value 160K  Tolerance: ±1%  (hidden comment: Thick Film)
Resistor SMD chip 160k Ohm 0.125W 1% 0805; Manufacturer 1: Vishay/Dale; Manufacturer Part Number 1: CRCW0805160KFKEA; Ratings: 1/8W; SCDType: spec
footprint RESC2012X70N (Chip Resistor, Body 2.0x1.2mm, 0805, IPC Medium Density)
pins: 1, 2

## RES_180R_0603_5%
designator R?, comment value 180R  (hidden comment: Thick Film)
Resistor SMD chip 180 Ohm 0.1W 5% 0603; Manufacturer 1: Vishay Dale; Manufacturer Part Number 1: CRCW0603180RJNEA; Ratings: 1/10 W; SCDType: spec
footprint RESC1608X55N (Chip Resistor, Body 1.6x0.8mm, 0603, IPC Medium Density)
pins: 1, 2

## RES_200R_0603_5%
designator R?, comment value 200R  (hidden comment: Thick Film)
Resistor SMD chip 200 Ohm 0.1W 5% 0603; Manufacturer 1: Yageo; Manufacturer Part Number 1: RC0603JR-07200RL; Ratings: 1/10 W; SCDType: undef
footprint RESC1608X55N (Chip Resistor, Body 1.6x0.8mm, 0603, IPC Medium Density)
pins: 1, 2

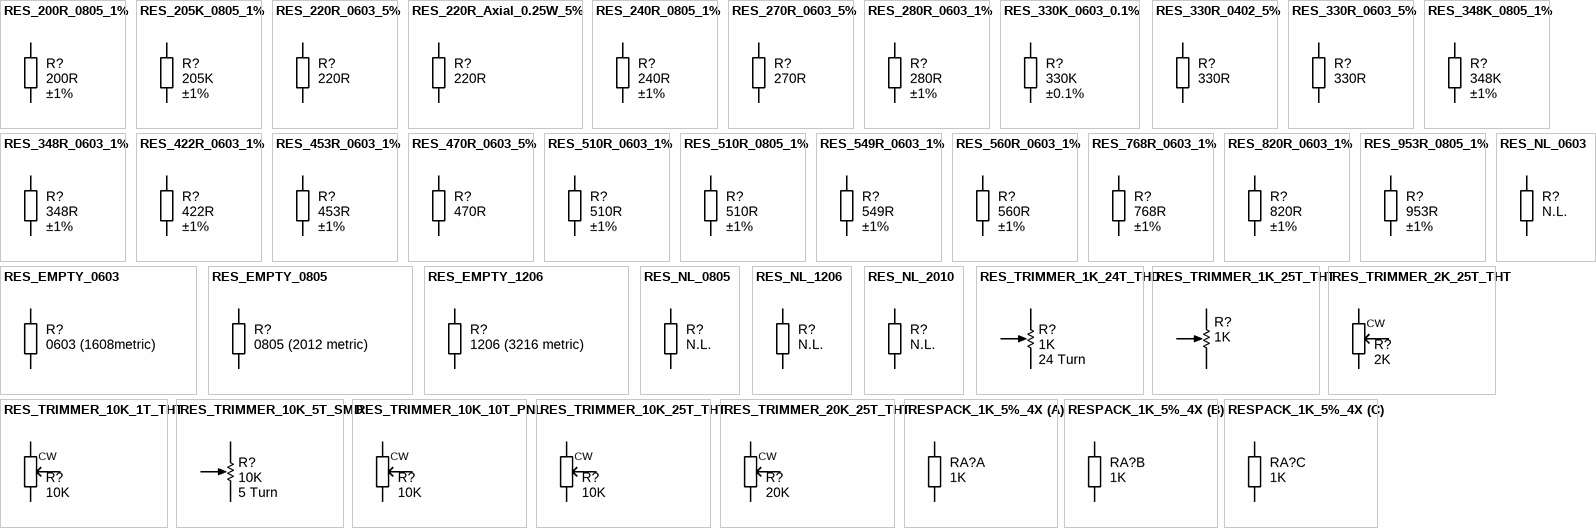
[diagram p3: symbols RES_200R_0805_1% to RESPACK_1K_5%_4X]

## RES_200R_0805_1%
designator R?, comment value 200R  Tolerance: ±1%  (hidden comment: Thick Film)
Resistor SMD chip 200 Ohm 0.125W 1% 0805; Manufacturer 1: Vishay/Dale; Manufacturer Part Number 1: CRCW0805200RFKEA; Ratings: 1/8W; SCDType: spec
footprint RESC2012X70N (Chip Resistor, Body 2.0x1.2mm, 0805, IPC Medium Density)
pins: 1, 2

## RES_205K_0805_1%
designator R?, comment value 205K  Tolerance: ±1%  (hidden comment: Thick Film)
Resistor SMD chip 205k Ohm 0.125W 1% 0805; Manufacturer 1: Vishay/Dale; Manufacturer Part Number 1: CRCW0805205KFKEA; Ratings: 1/8W; SCDType: spec
footprint RESC2012X70N (Chip Resistor, Body 2.0x1.2mm, 0805, IPC Medium Density)
pins: 1, 2

## RES_220R_0603_5%
designator R?, comment value 220R  (hidden comment: Thick Film)
Resistor SMD chip 220 Ohm 0.1W 5% 0603; Manufacturer 1: Yageo; Manufacturer Part Number 1: RC0603JR-07220RL; Ratings: 1/10 W; SCDType: spec
footprint RESC1608X55N (Chip Resistor, Body 1.6x0.8mm, 0603, IPC Medium Density)
pins: 1, 2

## RES_220R_Axial_0.25W_5%
designator R?, comment value 220R  (hidden comment: Carbon Film)
Resistor THD Axial 220 Ohm 0.25W 5% Carbon Film; Manufacturer 1: Yageo; Manufacturer Part Number 1: CFR-25JB-220R; Ratings: 1/4W; SCDType: spec
footprint RESTH_AXIAL-0.4
pins: 1, 2

## RES_240R_0805_1%
designator R?, comment value 240R  Tolerance: ±1%  (hidden comment: Thick Film)
Resistor SMD chip 240 Ohm 0.125W 1% 0805; Manufacturer 1: Vishay/Dale; Manufacturer Part Number 1: CRCW0805240RFKEA; Ratings: 1/8W; SCDType: spec
footprint RESC2012X70N (Chip Resistor, Body 2.0x1.2mm, 0805, IPC Medium Density)
pins: 1, 2

## RES_270R_0603_5%
designator R?, comment value 270R  (hidden comment: Thick Film)
Resistor SMD chip 270 Ohm 0.1W 5% 0603; Manufacturer 1: Yageo; Manufacturer Part Number 1: RC0603JR-07270RL; Ratings: 1/10 W; SCDType: undef
footprint RESC1608X55N (Chip Resistor, Body 1.6x0.8mm, 0603, IPC Medium Density)
pins: 1, 2

## RES_280R_0603_1%
designator R?, comment Tolerance: ±1%  (hidden comment: 280R)
Resistor SMD chip 280 Ohm 0.1W 1% 0603; Manufacturer 1: Yageo; Manufacturer Part Number 1: RC0603FR-07280RL; Ratings: 1/10W; SCDType: spec
footprint RESC1608X55N (Chip Resistor, Body 1.6x0.8mm, 0603, IPC Medium Density)
pins: 1, 2

## RES_330K_0603_0.1%
designator R?, comment value 330K  Tolerance: ±0.1%  (hidden comment: Thin Film)
Resistor SMD chip 330k Ohm 0.1W 0.1% 0603; Manufacturer 1: Panasonic - ECG; Manufacturer Part Number 1: ERA-3AEB334V; Ratings: 1/10 W; SCDType: undef
footprint RESC1608X55N (Chip Resistor, Body 1.6x0.8mm, 0603, IPC Medium Density)
pins: 1, 2

## RES_330R_0402_5%
designator R?, comment value 330R  (hidden comment: Thick Film)
Resistor SMD chip 330 Ohm 0.063W 5% 0402; Manufacturer 1: Yageo; Manufacturer Part Number 1: RC0402JR-07330RL; Ratings: 1/16 W; SCDType: spec
footprint RESC1005X40N (Chip Resistor, Body 1.0x0.5mm, EIA 0402, IPC Medium Density)
pins: 1, 2

## RES_330R_0603_5%
designator R?, comment value 330R  (hidden comment: Thick Film)
Resistor SMD chip 330 Ohm 0.1W 5% 0603; Manufacturer 1: Vishay Dale; Manufacturer Part Number 1: CRCW0603330RJNEA; Ratings: 1/10 W; SCDType: spec
footprint RESC1608X55N (Chip Resistor, Body 1.6x0.8mm, 0603, IPC Medium Density)
pins: 1, 2

## RES_348K_0805_1%
designator R?, comment value 348K  Tolerance: ±1%  (hidden comment: Thick Film)
Resistor SMD chip 348k Ohm 0.125W 1% 0805; Manufacturer 1: Vishay/Dale; Manufacturer Part Number 1: CRCW0805348KFKEA; Ratings: 1/8W; SCDType: spec
footprint RESC2012X70N (Chip Resistor, Body 2.0x1.2mm, 0805, IPC Medium Density)
pins: 1, 2

## RES_348R_0603_1%
designator R?, comment value 348R  Tolerance: ±1%  (hidden comment: Thin Film)
Resistor SMD chip 348 Ohm 0.1W 1% 0603; Manufacturer 1: Yageo; Manufacturer Part Number 1: RC0603FR-07348RL; Ratings: 1/10 W; SCDType: spec
footprint RESC1608X55N (Chip Resistor, Body 1.6x0.8mm, 0603, IPC Medium Density)
pins: 1, 2

## RES_422R_0603_1%
designator R?, comment value 422R  Tolerance: ±1%  (hidden comment: Thick Film)
Resistor SMD chip 422 Ohm 0.1W 1% 0603; Manufacturer 1: Yageo; Manufacturer Part Number 1: RC0603FR-07422RL; Ratings: 1/10W; SCDType: spec
footprint RESC1608X55N (Chip Resistor, Body 1.6x0.8mm, 0603, IPC Medium Density)
pins: 1, 2

## RES_453R_0603_1%
designator R?, comment value 453R  Tolerance: ±1%  (hidden comment: Thin Film)
Resistor SMD chip 453 Ohm 0.1W 1% 0603; Manufacturer 1: Yageo; Manufacturer Part Number 1: RC0603FR-07453RL; Ratings: 1/10 W; SCDType: spec
footprint RESC1608X55N (Chip Resistor, Body 1.6x0.8mm, 0603, IPC Medium Density)
pins: 1, 2

## RES_470R_0603_5%
designator R?, comment value 470R  (hidden comment: Thick Film)
Resistor SMD chip 470 Ohm 0.1W 5% 0603; Manufacturer 1: Vishay/Dale; Manufacturer Part Number 1: CRCW0603470RJNEA; Ratings: 1/10 W; SCDType: spec
footprint RESC1608X55N (Chip Resistor, Body 1.6x0.8mm, 0603, IPC Medium Density)
pins: 1, 2

## RES_510R_0603_1%
designator R?, comment value 510R  Tolerance: ±1%  (hidden comment: Thick Film)
Resistor SMD chip 510 Ohm 0.1W 1% 0603; Manufacturer 1: Yageo; Manufacturer Part Number 1: RC0603FR-07510RL; Ratings: 1/10 W; SCDType: spec
footprint RESC1608X55N (Chip Resistor, Body 1.6x0.8mm, 0603, IPC Medium Density)
pins: 1, 2

## RES_510R_0805_1%
designator R?, comment value 510R  Tolerance: ±1%  (hidden comment: Thick Film)
Resistor SMD chip 510 Ohm 0.125W 1% 0805; Manufacturer 1: Yageo; Manufacturer Part Number 1: RC0805FR-07510RL; Ratings: 1/8 W; SCDType: spec
footprint RESC2012X70N (Chip Resistor, Body 2.0x1.2mm, 0805, IPC Medium Density)
pins: 1, 2

## RES_549R_0603_1%
designator R?, comment value 549R  Tolerance: ±1%  (hidden comment: Thick Film)
Resistor SMD chip 549 Ohm 0.1W 1% 0603; Manufacturer 1: Yageo; Manufacturer Part Number 1: RC0603FR-07549RL; Ratings: 1/10W; SCDType: undef
footprint RESC1608X55N (Chip Resistor, Body 1.6x0.8mm, 0603, IPC Medium Density)
pins: 1, 2

## RES_560R_0603_1%
designator R?, comment Tolerance: ±1%  (hidden comment: 560R)
Resistor SMD chip 560 Ohm 0.1W 1% 0603; Manufacturer 1: Yageo; Manufacturer Part Number 1: RC0603FR-07560RL; Ratings: 1/10W; SCDType: spec
footprint RESC1608X55N (Chip Resistor, Body 1.6x0.8mm, 0603, IPC Medium Density)
pins: 1, 2

## RES_768R_0603_1%
designator R?, comment value 768R  Tolerance: ±1%  (hidden comment: Thick Film)
Resistor SMD chip 768 Ohm 0.1W 1% 0603; Manufacturer 1: Yageo; Manufacturer Part Number 1: RC0603FR-07768RL; Ratings: 1/10W; SCDType: spec
footprint RESC1608X55N (Chip Resistor, Body 1.6x0.8mm, 0603, IPC Medium Density)
pins: 1, 2

## RES_820R_0603_1%
designator R?, comment value 820R  Tolerance: ±1%  (hidden comment: Thick Film)
Resistor SMD chip 820 Ohm 0.1W 1% 0603; Manufacturer Part Number 1: RC0603FR-07820RL; Manufacturer 1: Yageo; Ratings: 1/10W; SCDType: undef
footprint RESC1608X55N (Chip Resistor, Body 1.6x0.8mm, 0603, IPC Medium Density)
pins: 1, 2

## RES_953R_0805_1%
designator R?, comment value 953R  Tolerance: ±1%  (hidden comment: Thick Film)
Resistor SMD chip 953 Ohm 0.125W 1% 0805; Manufacturer 1: Vishay/Dale; Manufacturer Part Number 1: CRCW0805953RFKEA; Ratings: 1/8W; SCDType: spec
footprint RESC2012X70N (Chip Resistor, Body 2.0x1.2mm, 0805, IPC Medium Density)
pins: 1, 2

## RES_EMPTY_0603
designator R?  Package / Case: 0603 (1608metric)  (hidden comment: *)
Resistor, 08603 SMD, Empty footprint
footprint RESC1608X55N (Chip Resistor, Body 1.6x0.8mm, 0603, IPC Medium Density)
pins: 1, 2

## RES_EMPTY_0805
designator R?  Package / Case: 0805 (2012 metric)  (hidden comment: *)
Resistor, 0805 SMD, Empty footprint
footprint RESC2012X70N (Chip Resistor, Body 2.0x1.2mm, 0805, IPC Medium Density)
pins: 1, 2

## RES_EMPTY_1206
designator R?  Package / Case: 1206 (3216 metric)  (hidden comment: *)
Resistor, 1206 SMD, Empty footprint
footprint RESC3216X70N (Chip Resistor, Body 3.2x1.6mm, 1206, IPC Medium Density)
pins: 1, 2

## RES_NL_0603
designator R?  value N.L.  (hidden comment: *)  (no BOM)
Resistor, SMD chip
footprint RESC1608X55N (Chip Resistor, Body 1.6x0.8mm, 0603, IPC Medium Density)
pins: 1, 2

## RES_NL_0805
designator R?  value N.L.  (hidden comment: *)  (no BOM)
Resistor, SMD chip
footprint RESC2012X70N (Chip Resistor, Body 2.0x1.2mm, 0805, IPC Medium Density)
pins: 1, 2

## RES_NL_1206
designator R?  value N.L.  (hidden comment: *)  (no BOM)
Resistor, SMD chip
footprint RESC3216X70N (Chip Resistor, Body 3.2x1.6mm, 1206, IPC Medium Density)
pins: 1, 2

## RES_NL_2010
designator R?  value N.L.  (hidden comment: *)  (no BOM)
Resistor, SMD chip
footprint RESC5025X70N (Chip Resistor, Body 5.0x2.5mm, 2010, IPC Medium Density)
pins: 1, 2

## RES_TRIMMER_1K_24T_THD
designator R?, comment 24 Turn  value 1K
Trimmer, 24-Turn, 1K; Manufacturer 1: VISHAY SPECTROL; Manufacturer Part Number 1: 64Y-102; Tolerance: 10%; Ratings: 24 turn variable cermet; SCDType: spec
footprint VishaySpectrol_64Y (VISHAY SPECTROL - 64Y - TRIMMER)
pins: 1 CCW, 2 TAP, 3 CW

## RES_TRIMMER_1K_25T_THT
designator R?, comment value 1K  (hidden comment: 25 Turn)
Trimmer, 25-Turn, 1K cermet; Manufacturer 1: Murata Electronics North America; Manufacturer Part Number 1: PV36Y102C01B00; Tolerance: 10%; Ratings: 25 turn variable cermet; SCDType: spec
footprint TrimPot_THT_2.54mm pitch (TRIMMER, MURATA, PV36Y)
pins: 1 CCW, 2 TAP, 3 CW

## RES_TRIMMER_2K_25T_THT
designator R?, comment value 2K  (hidden comment: 25 turns)
Trimmer THD 2K 500mW 25-turn; Manufacturer 1: Murata Electronics North America; Manufacturer Part Number 1: PV36X202C01B00; Tolerance: ±10%; Ratings: 1/2W; ±100ppm/°C; SCDType: spec
footprint TrimPot_THT_PV36X (TRIMMER, MURATA, PV36X)
pins: CCW 1, CW 3, W 2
